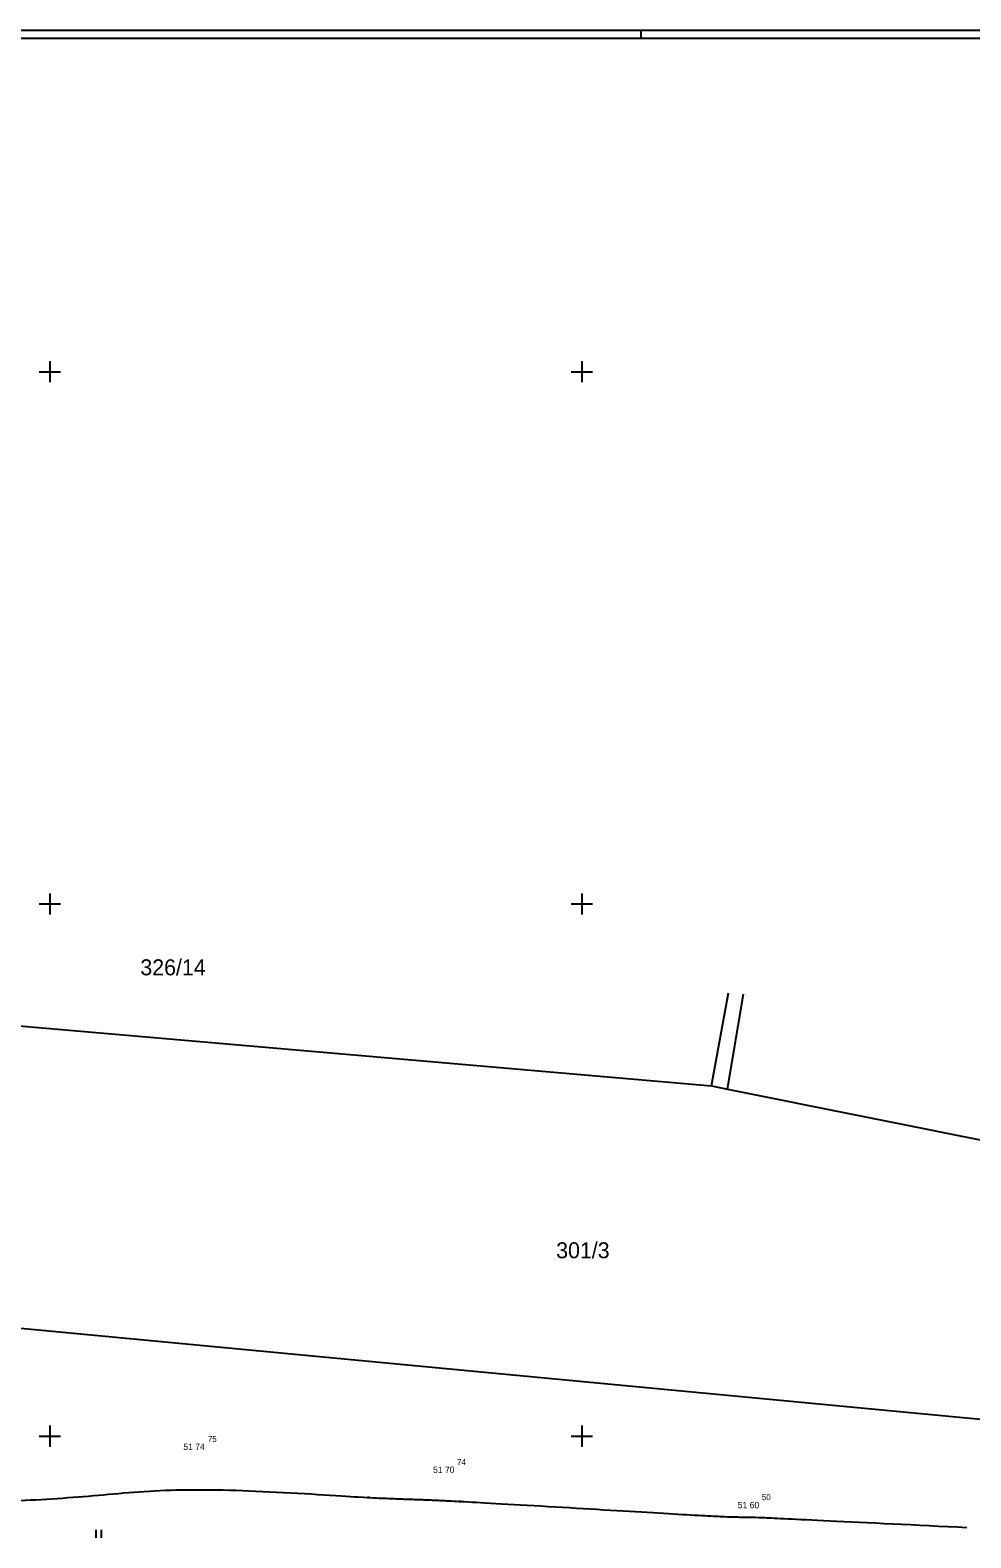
# Model space of a CAD drawing. Extents: x -704057 to -703795, y -1008732 to -1008584.
# Drawn here: x -703875.9 to -703831.7, y -1008654.8 to -1008584 of the extents above; entities that cross this region are included whole.
import ezdxf

# ---------------------------------------------------------------- set-up
doc = ezdxf.new("R2010")
doc.units = 0
for name, color, linetype in [('Z_body', 7, 'Continuous'), ('Z_body_cisla', 7, 'Continuous'), ('Z_body_vysky', 7, 'Continuous'), ('Z_hekt_sit', 7, 'Continuous'), ('Z_katastr_cisla_pozemkove', 7, 'Continuous'), ('Z_katastr_hranice', 7, 'Continuous'), ('Z_plotbox', 7, 'Continuous'), ('Z_popis', 7, 'Continuous'), ('Z_ramecek_tisk', 7, 'Continuous'), ('Z_vrstevnice_vedlejsi', 7, 'Continuous')]:
    doc.layers.add(name, color=color, linetype=linetype)

# ---------------------------------------------------------------- blocks, each defined once
blk = doc.blocks.new('POINT_DISPLAY')
blk.add_line((0, 0), (0, 0))
blk = doc.blocks.new('Z306')
for p, q in [((-0.13, 0.17), (-0.13, -0.2)), ((0.13, 0.17), (0.13, -0.2))]:
    blk.add_line(p, q)

msp = doc.modelspace()

# ---------------------------------------------------------------- linework, layer by layer
at = {"layer": 'Z_hekt_sit'}
for p, q in [((-703875, -1008599.5), (-703875, -1008600.5)), ((-703850, -1008599.5), (-703850, -1008600.5)), ((-703875.5, -1008600), (-703874.5, -1008600)), ((-703850.5, -1008600), (-703849.5, -1008600)), ((-703875, -1008624.5), (-703875, -1008625.5)), ((-703850, -1008624.5), (-703850, -1008625.5)), ((-703875.5, -1008625), (-703874.5, -1008625)), ((-703850.5, -1008625), (-703849.5, -1008625)), ((-703875, -1008649.5), (-703875, -1008650.5)), ((-703850, -1008649.5), (-703850, -1008650.5)), ((-703875.5, -1008650), (-703874.5, -1008650)), ((-703850.5, -1008650), (-703849.5, -1008650))]:
    msp.add_line(p, q, dxfattribs=at)
at = {"layer": 'Z_katastr_hranice'}
for p, q in [((-703894.73, -1008629.15), (-703843.9, -1008633.54)), ((-703843.9, -1008633.54), (-703843.11, -1008629.18)), ((-703843.15, -1008633.69), (-703842.4, -1008629.24)), ((-703843.9, -1008633.54), (-703843.15, -1008633.69)), ((-703843.15, -1008633.69), (-703811.75, -1008640)), ((-703807.93, -1008651.42), (-703891.93, -1008643.46))]:
    msp.add_line(p, q, dxfattribs=at)
at = {"layer": 'Z_plotbox'}
for p, q in [((-704057.23, -1008583.96), (-703794.73, -1008583.96)), ((-703847.23, -1008583.96), (-703847.23, -1008584.34))]:
    msp.add_line(p, q, dxfattribs=at)
at = {"layer": 'Z_ramecek_tisk'}
msp.add_line((-704056.86, -1008584.34), (-703795.11, -1008584.34), dxfattribs=at)
at = {"layer": 'Z_vrstevnice_vedlejsi'}
msp.add_open_spline([(-704009.362, -1008633.586), (-704007.915, -1008634.739), (-704007.143, -1008635.358), (-704002.876, -1008638.286), (-704002.679, -1008638.43), (-704002.255, -1008638.718), (-704001.165, -1008638.717), (-703995.889, -1008642.289), (-703994.89, -1008642.862), (-703994.417, -1008642.752), (-703993.832, -1008642.719), (-703993.258, -1008640.696), (-703993.341, -1008639.701), (-703993.272, -1008639.432), (-703993.04, -1008638.835), (-703992.99, -1008638.745), (-703990.403, -1008638.423), (-703989.481, -1008638.539), (-703989.058, -1008638.588), (-703989.018, -1008638.516), (-703988.578, -1008638.54), (-703988.475, -1008638.554), (-703988.362, -1008638.685), (-703988.319, -1008638.754), (-703988.294, -1008638.815), (-703986.637, -1008641.391), (-703986.518, -1008641.581), (-703985.267, -1008643.657), (-703984.422, -1008644.955), (-703982.223, -1008646.72), (-703982.083, -1008646.9), (-703980.47, -1008647.779), (-703979.335, -1008647.914), (-703971.793, -1008648.878), (-703969.312, -1008649.063), (-703968.076, -1008649.117), (-703960.948, -1008649.919), (-703959.282, -1008650.186), (-703958.493, -1008650.28), (-703957.367, -1008650.455), (-703955.116, -1008650.684), (-703950.816, -1008651.182), (-703948.3, -1008651.463), (-703946.953, -1008651.576), (-703945.397, -1008651.505), (-703943.023, -1008651.703), (-703939.161, -1008651.987), (-703938.27, -1008652.079), (-703937.191, -1008652.194), (-703934.147, -1008651.524), (-703931.028, -1008650.815), (-703930.717, -1008650.764), (-703928.94, -1008650.83), (-703928.501, -1008650.751), (-703928.424, -1008650.713), (-703928.413, -1008650.708), (-703928.266, -1008650.724), (-703926.027, -1008648.737), (-703920.5, -1008648.624), (-703915.824, -1008649.925), (-703908.88, -1008649.843), (-703904.651, -1008650.155), (-703897.103, -1008651.333), (-703893.743, -1008651.997), (-703889.99, -1008652.252), (-703881.693, -1008653.228), (-703874.656, -1008652.961), (-703868.448, -1008652.365), (-703859.857, -1008652.906), (-703856.36, -1008653.001), (-703843.765, -1008653.766), (-703842.17, -1008653.801), (-703841.143, -1008653.824), (-703831.904, -1008654.28)], degree=2, dxfattribs=at)

# ---------------------------------------------------------------- block references
at = {"layer": 'Z_body'}
for p in [(-703868.07, -1008650.34), (-703856.36, -1008651.42), (-703842.04, -1008653.08)]:
    msp.add_blockref('POINT_DISPLAY', p, dxfattribs=at)
at = {"layer": 'Z_popis'}
msp.add_blockref('Z306', (-703872.71, -1008654.57), dxfattribs=at)

# ---------------------------------------------------------------- texts
at = {"layer": 'Z_body_cisla'}
for s, p in [('75', (-703867.57, -1008650.27)), ('74', (-703855.86, -1008651.35)), ('50', (-703841.54, -1008653))]:
    msp.add_text(s, height=0.28, dxfattribs=at).set_placement(p)
at = {"layer": 'Z_body_vysky'}
for s, p in [('51 74', (-703868.72, -1008650.64)), ('51 70', (-703856.985, -1008651.72)), ('51 60', (-703842.665, -1008653.38))]:
    msp.add_text(s, height=0.3, dxfattribs=at).set_placement(p)
at = {"layer": 'Z_katastr_cisla_pozemkove'}
for s, p in [('326/14', (-703870.74, -1008628.35)), ('301/3', (-703851.2, -1008641.64))]:
    msp.add_text(s, height=0.75, dxfattribs=at).set_placement(p)

doc.saveas('drawing.dxf')
